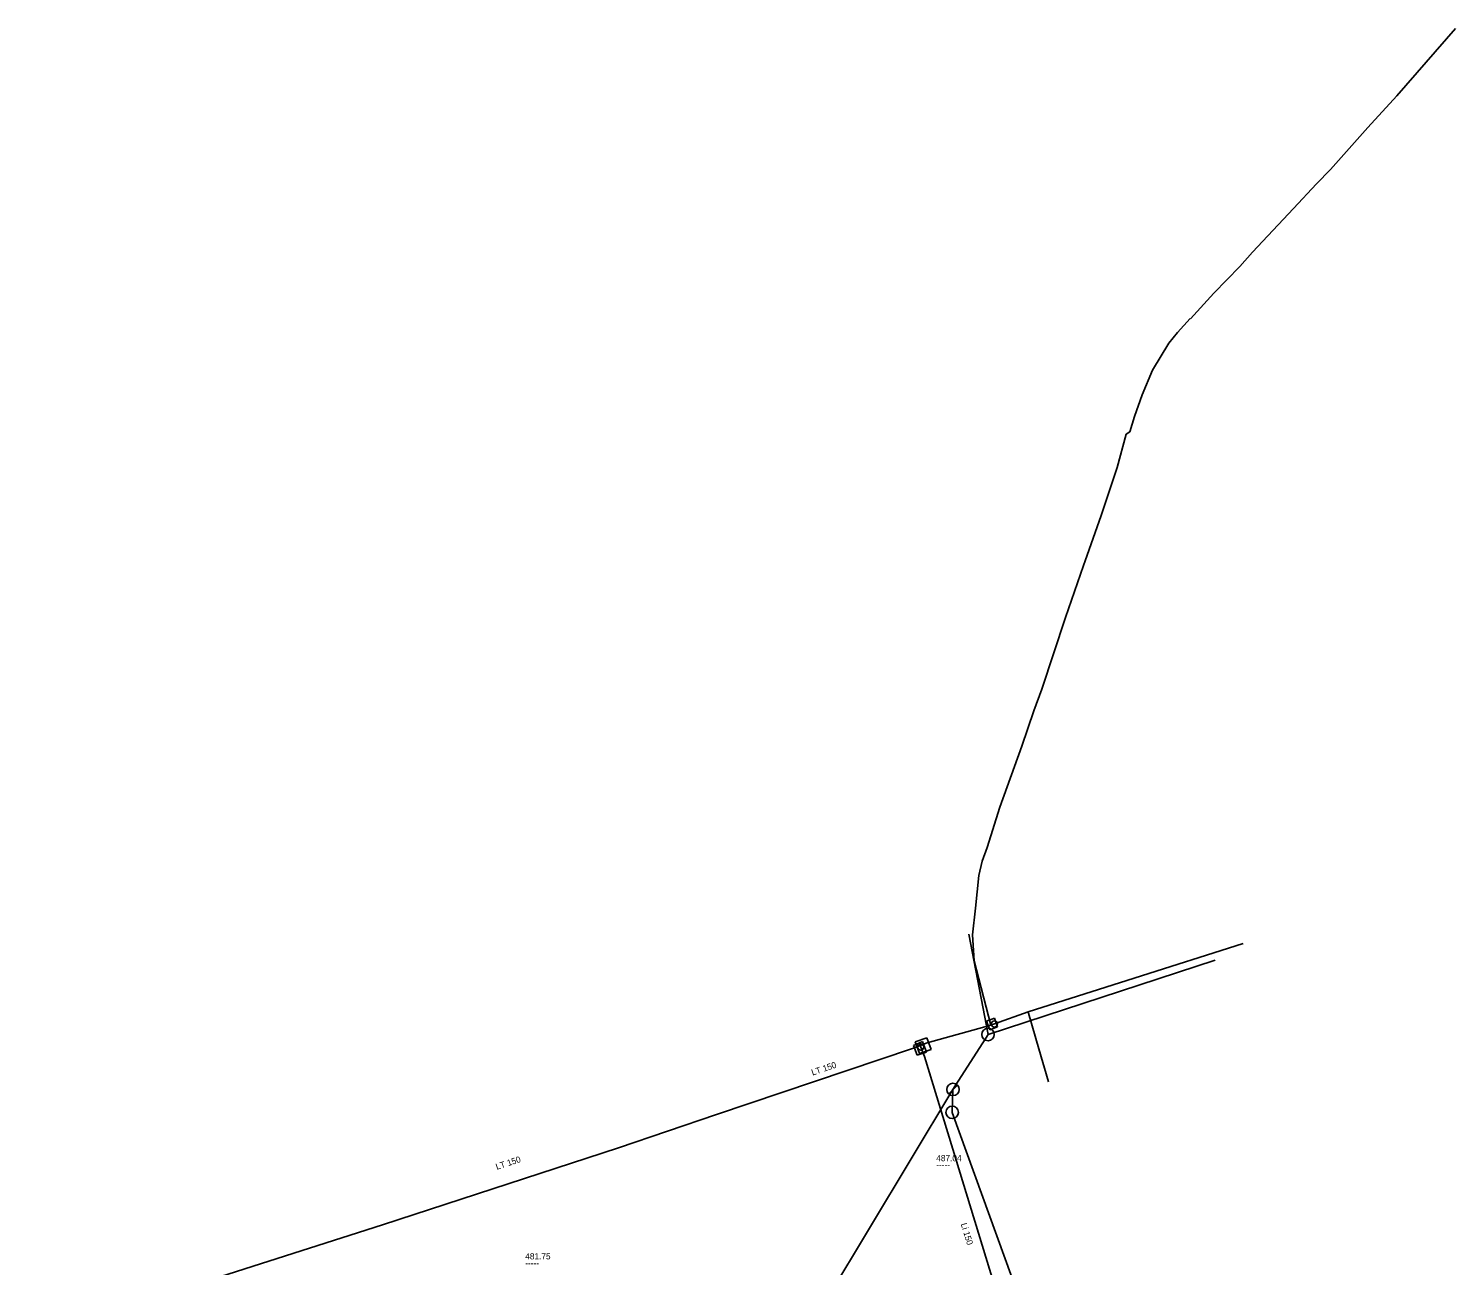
# Model space of a CAD drawing. Extents: x -685576 to -685145, y -1163436 to -1162895.
# Drawn here: x -685564.7 to -685334.1, y -1163094.7 to -1162894.9 of the extents above; entities that cross this region are included whole.
import ezdxf

# ---------------------------------------------------------------- set-up
doc = ezdxf.new("R2010")
doc.units = 0
doc.layers.add('Level 0', color=7, linetype='Continuous')

msp = doc.modelspace()

# ---------------------------------------------------------------- linework, layer by layer
at = {"layer": 'Level 0'}
for p, q in [((-685334.12, -1162894.92), (-685343.6, -1162905.78)), ((-685343.6, -1162905.78), (-685348.26, -1162910.89)), ((-685348.26, -1162910.89), (-685354.31, -1162917.66)), ((-685354.31, -1162917.66), (-685356.59, -1162919.99)), ((-685356.59, -1162919.99), (-685360.29, -1162924.01)), ((-685360.29, -1162924.01), (-685366.91, -1162931.03)), ((-685366.91, -1162931.03), (-685368.95, -1162933.37)), ((-685368.95, -1162933.37), (-685373.17, -1162937.67)), ((-685373.17, -1162937.67), (-685376.93, -1162941.79)), ((-685376.97, -1162941.75), (-685379, -1162944)), ((-685376.93, -1162941.79), (-685376.97, -1162941.75)), ((-685379, -1162944), (-685380.4, -1162945.74)), ((-685380.4, -1162945.74), (-685383.06, -1162950.09)), ((-685383.06, -1162950.09), (-685384.76, -1162954.07)), ((-685384.76, -1162954.07), (-685385.96, -1162957.58)), ((-685385.96, -1162957.58), (-685386.73, -1162960.07)), ((-685387.32, -1162960.42), (-685388.78, -1162965.81)), ((-685386.73, -1162960.07), (-685387.32, -1162960.42)), ((-685388.78, -1162965.81), (-685391.35, -1162973.57)), ((-685391.35, -1162973.57), (-685393.95, -1162980.91)), ((-685394.19, -1162981.63), (-685397.14, -1162990.04)), ((-685393.95, -1162980.91), (-685394.19, -1162981.63)), ((-685397.14, -1162990.04), (-685400.94, -1163001.59)), ((-685400.94, -1163001.59), (-685402.22, -1163005.13)), ((-685402.22, -1163005.13), (-685404.17, -1163010.82)), ((-685404.17, -1163010.82), (-685407.71, -1163020.66)), ((-685407.71, -1163020.66), (-685409.8, -1163027.19)), ((-685409.8, -1163027.19), (-685410.57, -1163029.41)), ((-685410.57, -1163029.41), (-685411.13, -1163031.71)), ((-685411.13, -1163031.71), (-685411.68, -1163036.96)), ((-685411.68, -1163036.96), (-685412.16, -1163041.28)), ((-685412.75, -1163041.19), (-685409.64, -1163057.39)), ((-685412.16, -1163041.28), (-685411.87, -1163045.49)), ((-685386.05, -1163048.29), (-685368.43, -1163042.71)), ((-685411.87, -1163045.49), (-685409.16, -1163055.9)), ((-685372.95, -1163045.37), (-685409.64, -1163057.39)), ((-685403.16, -1163053.71), (-685386.05, -1163048.29)), ((-685408.6, -1163055.69), (-685403.16, -1163053.71)), ((-685403.16, -1163053.71), (-685403.11, -1163053.94)), ((-685409.16, -1163055.9), (-685419.45, -1163058.72)), ((-685408.59, -1163054.77), (-685409.9, -1163055.21)), ((-685409.9, -1163055.21), (-685409.36, -1163056.66)), ((-685409.16, -1163055.9), (-685408.6, -1163055.69)), ((-685408.09, -1163056.16), (-685408.59, -1163054.77)), ((-685403.11, -1163053.94), (-685401.43, -1163059.72)), ((-685419.52, -1163057.91), (-685421.4, -1163058.59)), ((-685418.84, -1163059.79), (-685419.52, -1163057.91)), ((-685409.64, -1163057.39), (-685415.3, -1163066.26)), ((-685409.36, -1163056.66), (-685408.09, -1163056.16)), ((-685453.48, -1163070.32), (-685421.84, -1163059.63)), ((-685420.6, -1163059.15), (-685421.84, -1163059.63)), ((-685420.23, -1163058.5), (-685421.7, -1163059.18)), ((-685421.7, -1163059.18), (-685421.08, -1163060.71)), ((-685421.4, -1163058.59), (-685420.72, -1163060.47)), ((-685421.08, -1163060.71), (-685419.58, -1163060.23)), ((-685420.72, -1163060.47), (-685418.84, -1163059.79)), ((-685419.45, -1163058.72), (-685420.6, -1163059.15)), ((-685420.6, -1163059.15), (-685420.52, -1163059.42)), ((-685420.52, -1163059.42), (-685419.92, -1163060.93)), ((-685419.58, -1163060.23), (-685420.23, -1163058.5)), ((-685401.43, -1163059.72), (-685399.89, -1163065.02)), ((-685419.92, -1163060.93), (-685400.96, -1163122.89)), ((-685415.3, -1163066.26), (-685441.48, -1163109.74)), ((-685415.99, -1163066.98), (-685414.58, -1163065.58)), ((-685415.3, -1163066.26), (-685415.43, -1163069.96)), ((-685469.36, -1163075.69), (-685453.48, -1163070.32)), ((-685415.43, -1163069.96), (-685403.36, -1163103.27)), ((-685507.45, -1163088.13), (-685469.36, -1163075.69)), ((-685564.65, -1163106.35), (-685507.45, -1163088.13))]:
    msp.add_line(p, q, dxfattribs=at)
for centre, radius in [((-685408.6, -1163055.69), 0.5), ((-685409.64, -1163057.39), 1), ((-685420.52, -1163059.42), 0.5), ((-685415.3, -1163066.26), 1), ((-685415.43, -1163069.96), 1)]:
    msp.add_circle(centre, radius, dxfattribs=at)

# ---------------------------------------------------------------- texts
for s, rotation, p in [('LT 150', 18.668, (-685437.98, -1163064.03)), ('LT 150', 18.087, (-685488.99, -1163079.25)), ('Li 150', 287.015, (-685414.05, -1163088))]:
    msp.add_text(s, height=1, rotation=rotation, dxfattribs=at).set_placement(p)
for s, p in [('487.04', (-685418, -1163077.85)), ('-----', (-685418, -1163078.95)), ('481.75', (-685484.4, -1163093.71)), ('-----', (-685484.4, -1163094.81))]:
    msp.add_text(s, height=1, dxfattribs=at).set_placement(p)

doc.saveas('drawing.dxf')
